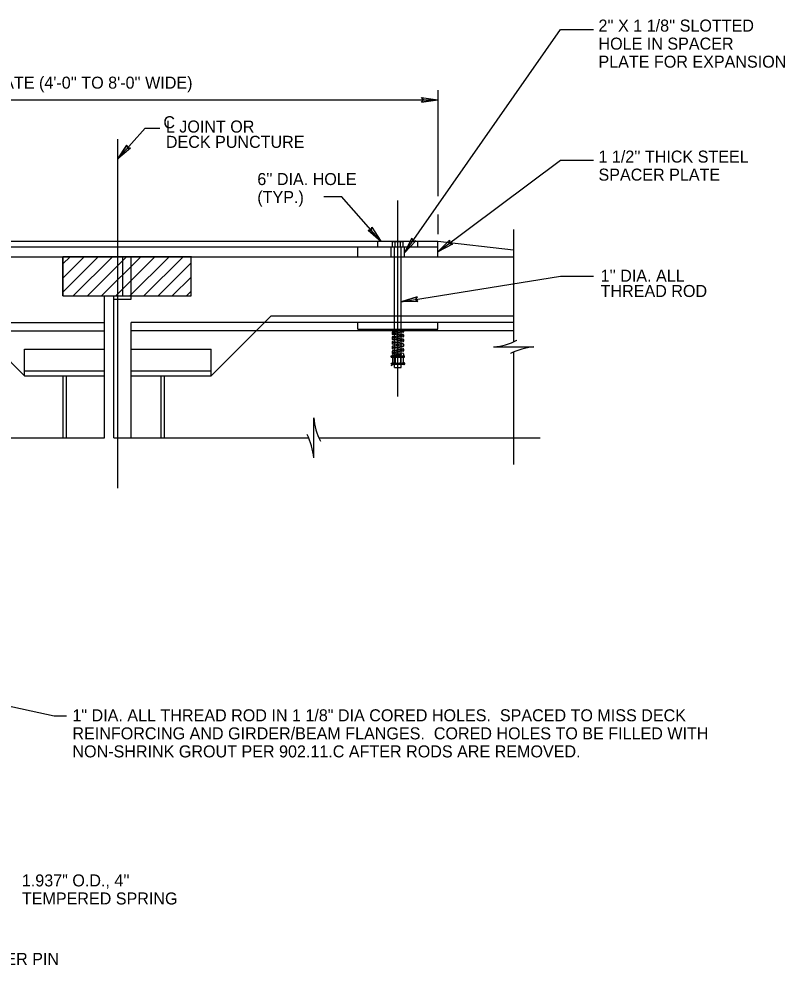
# Model space of a CAD drawing. Extents: x 12.49 to 19.62, y 5.98 to 15.32.
# Drawn here: x 15.532 to 19.35, y 10.606 to 15.325 of the extents above; entities that cross this region are included whole.
import ezdxf

# ---------------------------------------------------------------- set-up
doc = ezdxf.new("R2010")
doc.units = 0
for name, color, linetype in [('2', 7, 'Continuous'), ('Default', 7, 'Continuous'), ('DETL-DIMS', 7, 'Continuous'), ('DETL-NOTE', 7, 'Continuous'), ('V7_LEVEL_1', 7, 'Continuous')]:
    doc.layers.add(name, color=color, linetype=linetype)

msp = doc.modelspace()

# ---------------------------------------------------------------- linework, layer by layer
at = {"layer": '2'}
msp.add_line((17.6199, 14.2161), (17.9977, 14.1728), dxfattribs=at)
at = {"layer": 'Default'}
for p, q in [((17.4538, 14.1581), (18.2306, 15.2715)), ((18.2306, 15.2715), (18.3958, 15.2715)), ((17.6199, 14.9686), (17.6199, 14.4401)), ((14.4313, 14.9207), (17.6199, 14.9207)), ((16.0256, 14.6263), (16.1607, 14.7793)), ((16.1607, 14.7793), (16.2344, 14.7793)), ((16.0256, 12.9846), (16.0256, 14.7257)), ((17.6199, 14.1624), (18.2306, 14.6205)), ((18.2306, 14.6205), (18.3958, 14.6205)), ((17.051, 14.4391), (17.1394, 14.4391)), ((17.3356, 14.217), (17.1394, 14.4391)), ((17.4206, 13.4412), (17.4206, 14.4197)), ((17.6199, 14.3486), (17.6199, 14.2511)), ((17.9977, 14.2752), (17.9977, 13.714)), ((14.4313, 14.217), (17.6199, 14.217)), ((17.321, 14.188), (17.321, 14.217)), ((17.394, 14.188), (17.394, 14.2112)), ((17.4007, 14.2145), (17.4073, 14.2145)), ((17.4073, 14.2145), (17.4339, 14.2145)), ((17.4073, 14.188), (17.4073, 14.2112)), ((17.4339, 14.2145), (17.4405, 14.2145)), ((17.4339, 14.188), (17.4339, 14.2112)), ((17.4472, 14.188), (17.4472, 14.2112)), ((17.5203, 14.188), (17.5203, 14.217)), ((17.6199, 14.1381), (17.6199, 14.217)), ((14.8298, 14.188), (17.2213, 14.188)), ((17.2213, 14.1381), (17.2213, 14.188)), ((17.2213, 14.188), (17.6199, 14.188)), ((17.3874, 14.1381), (17.3874, 14.188)), ((17.404, 13.6037), (17.404, 14.188)), ((17.4372, 13.6037), (17.4372, 14.188)), ((17.4538, 14.1381), (17.4538, 14.188)), ((14.4313, 14.1381), (17.6199, 14.1381)), ((15.7515, 13.943), (15.7515, 14.1381)), ((15.7515, 14.1027), (15.787, 14.1381)), ((15.7515, 14.0322), (15.8575, 14.1381)), ((15.7515, 13.9618), (15.9279, 14.1381)), ((15.8032, 13.943), (15.9984, 14.1381)), ((15.8737, 13.943), (16.0688, 14.1381)), ((15.9442, 13.943), (16.1393, 14.1381)), ((16.0146, 13.943), (16.2098, 14.1381)), ((16.0505, 13.943), (16.0505, 14.1381)), ((16.0851, 13.943), (16.2802, 14.1381)), ((16.092, 13.9264), (16.092, 14.1381)), ((16.1555, 13.943), (16.3507, 14.1381)), ((16.3909, 13.943), (16.3909, 14.1423)), ((17.6199, 14.1381), (17.9977, 14.1381)), ((16.226, 13.943), (16.3909, 14.108)), ((16.2965, 13.943), (16.3909, 14.0375)), ((17.4372, 13.9142), (18.2306, 14.0418)), ((18.2306, 14.0418), (18.3958, 14.0418)), ((15.7515, 13.943), (15.9591, 13.943)), ((15.9591, 13.943), (16.092, 13.943)), ((15.9591, 13.2352), (15.9591, 13.943)), ((16.0048, 13.2352), (16.0048, 13.943)), ((16.0048, 13.9264), (16.092, 13.9264)), ((16.092, 13.943), (16.3909, 13.943)), ((16.3669, 13.943), (16.3909, 13.967)), ((15.5606, 13.5444), (15.2616, 13.8434)), ((16.4906, 13.5444), (16.7895, 13.8434)), ((16.7895, 13.8434), (17.9977, 13.8434)), ((14.8298, 13.8101), (15.9591, 13.8101)), ((16.092, 13.2352), (16.092, 13.8101)), ((17.2213, 13.8101), (16.092, 13.8101)), ((17.2213, 13.7769), (17.2213, 13.8101)), ((17.6199, 13.8101), (17.2213, 13.8101)), ((17.6199, 13.7769), (17.6199, 13.8101)), ((17.9977, 13.8101), (17.6199, 13.8101)), ((14.0119, 13.7686), (15.9591, 13.7686)), ((17.9977, 13.7686), (16.092, 13.7686)), ((17.2213, 13.7769), (17.6199, 13.7769)), ((17.3922, 13.7749), (17.3922, 13.7707)), ((17.3922, 13.7612), (17.3922, 13.7525)), ((17.3922, 13.7375), (17.3922, 13.7288)), ((17.4379, 13.7676), (17.394, 13.7633)), ((17.4438, 13.7455), (17.394, 13.7504)), ((17.4438, 13.7445), (17.394, 13.7396)), ((17.4472, 13.7622), (17.3974, 13.7574)), ((17.4472, 13.7514), (17.3974, 13.7563)), ((17.4472, 13.7386), (17.3974, 13.7337)), ((17.4472, 13.7278), (17.3974, 13.7326)), ((17.4491, 13.7749), (17.4491, 13.7643)), ((17.4491, 13.7494), (17.4491, 13.7406)), ((17.3922, 13.7139), (17.3922, 13.7051)), ((17.3922, 13.6902), (17.3922, 13.6814)), ((17.4438, 13.7218), (17.394, 13.7267)), ((17.4438, 13.7208), (17.394, 13.7159)), ((17.4438, 13.6982), (17.394, 13.703)), ((17.4438, 13.6971), (17.394, 13.6923)), ((17.4472, 13.7149), (17.3974, 13.71)), ((17.4472, 13.7041), (17.3974, 13.709)), ((17.4472, 13.6912), (17.3974, 13.6863)), ((17.4472, 13.6804), (17.3974, 13.6853)), ((17.4491, 13.7257), (17.4491, 13.717)), ((17.4491, 13.702), (17.4491, 13.6933)), ((17.8981, 13.6887), (17.9977, 13.6887)), ((17.9977, 13.6887), (18.0974, 13.6887)), ((17.9977, 13.6887), (17.9977, 13.6887)), ((18.0143, 13.722), (18.0143, 13.722)), ((15.5606, 13.6773), (15.9591, 13.6773)), ((15.5606, 13.5444), (15.5606, 13.6773)), ((16.092, 13.6773), (16.4906, 13.6773)), ((16.4906, 13.5444), (16.4906, 13.6773)), ((17.3874, 13.6441), (17.4538, 13.6441)), ((17.3874, 13.6378), (17.3874, 13.6441)), ((17.3874, 13.6378), (17.4538, 13.6378)), ((17.3922, 13.6665), (17.3922, 13.6578)), ((17.3922, 13.6482), (17.3922, 13.6461)), ((17.4438, 13.6745), (17.394, 13.6794)), ((17.4438, 13.6735), (17.394, 13.6686)), ((17.4385, 13.6513), (17.394, 13.6557)), ((17.3942, 13.6503), (17.4384, 13.6503)), ((17.4472, 13.6675), (17.3974, 13.6627)), ((17.4472, 13.6567), (17.3974, 13.6616)), ((17.4491, 13.6783), (17.4491, 13.6696)), ((17.4491, 13.6547), (17.4491, 13.6461)), ((17.4538, 13.6378), (17.4538, 13.6441)), ((17.9811, 13.6555), (17.9811, 13.6555)), ((17.9977, 13.6635), (17.9977, 13.1023)), ((17.3865, 13.6079), (17.4466, 13.6079)), ((17.3865, 13.6058), (17.3865, 13.6079)), ((17.3865, 13.6058), (17.4507, 13.6058)), ((17.3868, 13.5978), (17.4005, 13.6058)), ((17.3868, 13.5978), (17.3878, 13.596)), ((17.3878, 13.596), (17.4011, 13.6037)), ((17.394, 13.6345), (17.394, 13.6113)), ((17.4007, 13.6079), (17.4073, 13.6079)), ((17.4011, 13.6037), (17.4466, 13.6037)), ((17.404, 13.5861), (17.404, 13.6037)), ((17.4073, 13.6345), (17.4073, 13.6113)), ((17.4073, 13.6079), (17.4339, 13.6079)), ((17.4339, 13.6345), (17.4339, 13.6113)), ((17.4339, 13.6079), (17.4405, 13.6079)), ((17.4372, 13.5861), (17.4372, 13.6037)), ((17.4472, 13.6345), (17.4472, 13.6113)), ((15.5606, 13.5693), (15.9591, 13.5693)), ((15.5606, 13.5444), (15.9591, 13.5444)), ((15.7515, 13.5444), (15.7515, 13.2352)), ((15.7682, 13.5444), (15.7682, 13.2352)), ((16.092, 13.5693), (16.4906, 13.5693)), ((16.092, 13.5444), (16.4906, 13.5444)), ((16.2394, 13.5444), (16.2394, 13.2352)), ((16.256, 13.5444), (16.256, 13.2352)), ((17.404, 13.5861), (17.4372, 13.5861)), ((17.0013, 13.2352), (17.0013, 13.3348)), ((15.0108, 13.2352), (15.9591, 13.2352)), ((16.0048, 13.2352), (16.976, 13.2352)), ((16.9681, 13.2518), (16.9681, 13.2518)), ((17.0013, 13.1356), (17.0013, 13.2352)), ((17.0013, 13.2352), (17.0013, 13.2352)), ((17.0265, 13.2352), (18.1306, 13.2352)), ((17.0345, 13.2186), (17.0345, 13.2186)), ((14.4538, 12.12), (15.7083, 11.8493)), ((15.7083, 11.8493), (15.7687, 11.8493))]:
    msp.add_line(p, q, dxfattribs=at)
msp.add_lwpolyline([(15.7515, 13.943), (16.3909, 13.943), (16.3909, 14.1381), (15.7515, 14.1381)], close=True, dxfattribs=at)
msp.add_circle((17.4512, 13.6058), 0.000514, dxfattribs=at)
for centre, radius, start, end in [((17.4007, 14.2063), 0.00822, 36.0721, 143.9279), ((17.4206, 14.1867), 0.0278, 61.4571, 118.5429), ((17.4405, 14.2063), 0.00822, 36.0721, 143.9279), ((17.3942, 13.7749), 0.00208, 90, 180), ((17.3942, 13.7707), 0.00208, 180, 270), ((17.3942, 13.7612), 0.00208, 95.6019, 180), ((17.3942, 13.7525), 0.00208, 180, 264.3981), ((17.3942, 13.7375), 0.00208, 95.6019, 180), ((17.3975, 13.7568), 0.000519, 95.6019, 264.3982), ((17.3975, 13.7332), 0.000519, 95.6019, 264.3982), ((17.4379, 13.7681), 0.000519, 275.6019, 90), ((17.4437, 13.745), 0.000519, 275.6019, 84.3982), ((17.447, 13.7749), 0.00208, 0, 90), ((17.447, 13.7707), 0.00208, 270, 0), ((17.447, 13.7643), 0.00208, 275.6019, 0), ((17.447, 13.7494), 0.00208, 360, 84.3981), ((17.447, 13.7406), 0.00208, 275.6019, 0), ((17.3942, 13.7288), 0.00208, 180, 264.3981), ((17.3942, 13.7139), 0.00208, 95.6019, 180), ((17.3942, 13.7051), 0.00208, 180, 264.3981), ((17.3942, 13.6902), 0.00208, 95.6019, 180), ((17.3975, 13.7095), 0.000519, 95.6019, 264.3982), ((17.3975, 13.6858), 0.000519, 95.6018, 264.3981), ((17.4437, 13.7213), 0.000519, 275.6019, 84.3982), ((17.4437, 13.6976), 0.000519, 275.6019, 84.3982), ((17.447, 13.7257), 0.00208, 360, 84.3981), ((17.447, 13.717), 0.00208, 275.6019, 0), ((17.447, 13.702), 0.00208, 360, 84.3981), ((17.447, 13.6933), 0.00208, 275.6018, 0), ((17.8736, 13.9943), 0.3065, 274.5716, 297.3191), ((18.1218, 13.3832), 0.3065, 94.5716, 117.3191), ((17.3942, 13.6814), 0.00208, 180, 264.3981), ((17.3942, 13.6665), 0.00208, 95.6019, 180), ((17.3942, 13.6578), 0.00208, 180, 264.3981), ((17.3942, 13.6482), 0.00208, 90, 180), ((17.3942, 13.6461), 0.00208, 180, 270), ((17.4007, 13.6296), 0.00822, 36.0721, 143.9279), ((17.3975, 13.6621), 0.000519, 95.6019, 264.3982), ((17.4206, 13.61), 0.0278, 61.4571, 118.5429), ((17.4405, 13.6296), 0.00822, 36.0721, 143.9279), ((17.4384, 13.6508), 0.000519, 270, 84.3981), ((17.4437, 13.674), 0.000519, 275.6019, 84.3982), ((17.447, 13.6461), 0.00208, 270, 0), ((17.447, 13.6783), 0.00208, 0, 84.3981), ((17.447, 13.6696), 0.00208, 275.6019, 0), ((17.447, 13.6547), 0.00208, 0, 84.3981), ((17.4007, 13.6161), 0.00822, 216.0721, 323.9279), ((17.4206, 13.6357), 0.0278, 241.4571, 298.5429), ((17.4405, 13.6161), 0.00822, 216.0721, 323.9279), ((17.4466, 13.61), 0.00208, 270, 318.007), ((17.4466, 13.6017), 0.00208, 41.6281, 90), ((17.4512, 13.6058), 0.00415, 221.6281, 138.007), ((17.3068, 13.3593), 0.3065, 184.5716, 207.3191), ((16.6957, 13.1111), 0.3065, 4.5716, 27.3191)]:
    msp.add_arc(centre, radius, start, end, dxfattribs=at)
at = {"layer": 'DETL-DIMS'}
for p, q in [((17.5381, 14.9326), (17.6199, 14.9207)), ((17.5381, 14.9326), (17.5482, 14.9207)), ((17.5381, 14.9088), (17.6199, 14.9207)), ((17.5381, 14.9088), (17.5482, 14.9207)), ((16.0708, 14.6955), (16.0256, 14.6263)), ((16.0887, 14.6797), (16.0256, 14.6263)), ((16.0708, 14.6955), (16.073, 14.68)), ((16.0887, 14.6797), (16.073, 14.68)), ((17.2725, 14.2704), (17.2881, 14.2708)), ((17.2725, 14.2704), (17.3356, 14.217)), ((17.2903, 14.2862), (17.2881, 14.2708)), ((17.2903, 14.2862), (17.3356, 14.217)), ((17.4909, 14.232), (17.4538, 14.1581)), ((17.5104, 14.2184), (17.4538, 14.1581)), ((17.4909, 14.232), (17.4948, 14.2169)), ((17.5104, 14.2184), (17.4948, 14.2169)), ((17.6782, 14.221), (17.6199, 14.1624)), ((17.6782, 14.221), (17.6773, 14.2055)), ((17.6925, 14.202), (17.6773, 14.2055)), ((17.6925, 14.202), (17.6199, 14.1624)), ((17.5161, 13.9389), (17.4372, 13.9142)), ((17.5161, 13.9389), (17.508, 13.9256)), ((17.5199, 13.9154), (17.508, 13.9256)), ((17.5199, 13.9154), (17.4372, 13.9142))]:
    msp.add_line(p, q, dxfattribs=at)
for points in [[(17.5381, 14.9326), (17.6199, 14.9207), (17.5381, 14.9088), (17.5482, 14.9207)], [(16.0887, 14.6797), (16.0256, 14.6263), (16.0708, 14.6955), (16.073, 14.68)], [(17.2903, 14.2862), (17.3356, 14.217), (17.2725, 14.2704), (17.2881, 14.2708)], [(17.5104, 14.2184), (17.4538, 14.1581), (17.4909, 14.232), (17.4948, 14.2169)], [(17.6925, 14.202), (17.6199, 14.1624), (17.6782, 14.221), (17.6773, 14.2055)], [(17.5199, 13.9154), (17.4372, 13.9142), (17.5161, 13.9389), (17.508, 13.9256)]]:
    msp.add_lwpolyline(points, close=True, dxfattribs=at)
at = {"layer": 'V7_LEVEL_1'}
msp.add_line((17.3942, 13.7686), (17.447, 13.7686), dxfattribs=at)

# ---------------------------------------------------------------- texts
at = {"layer": 'DETL-NOTE'}
for s, p in [("2'' X 1 1/8'' SLOTTED ", (18.4204, 15.2615)), ('HOLE IN SPACER ', (18.4204, 15.1715)), ('PLATE FOR EXPANSION', (18.4204, 15.0815)), ("1'' THICK PLATE (4'-0'' TO 8'-0'' WIDE)", (14.9953, 14.9769)), ('C', (16.2521, 14.7796)), ('L JOINT OR ', (16.2645, 14.758)), ('DECK PUNCTURE', (16.2645, 14.6817)), ("1 1/2'' THICK STEEL ", (18.4204, 14.6081)), ("6'' DIA. HOLE", (16.7203, 14.4961)), ('SPACER PLATE', (18.4204, 14.5181)), ('(TYP.)', (16.7203, 14.4061)), ("1'' DIA. ALL ", (18.4312, 14.0142)), ('THREAD ROD', (18.4312, 13.9379)), ('1" DIA. ALL THREAD ROD IN 1 1/8" DIA CORED HOLES.  SPACED TO MISS DECK ', (15.7988, 11.8217)), ('REINFORCING AND GIRDER/BEAM FLANGES.  CORED HOLES TO BE FILLED WITH ', (15.7988, 11.7317)), ('NON-SHRINK GROUT PER 902.11.C AFTER RODS ARE REMOVED.', (15.7988, 11.6417)), ('1.937" O.D., 4\'\' ', (15.5469, 10.9982)), ('TEMPERED SPRING', (15.5469, 10.9082)), ('COTTER PIN', (15.2462, 10.6069))]:
    msp.add_text(s, height=0.06, dxfattribs=at).set_placement(p)

doc.saveas('drawing.dxf')
